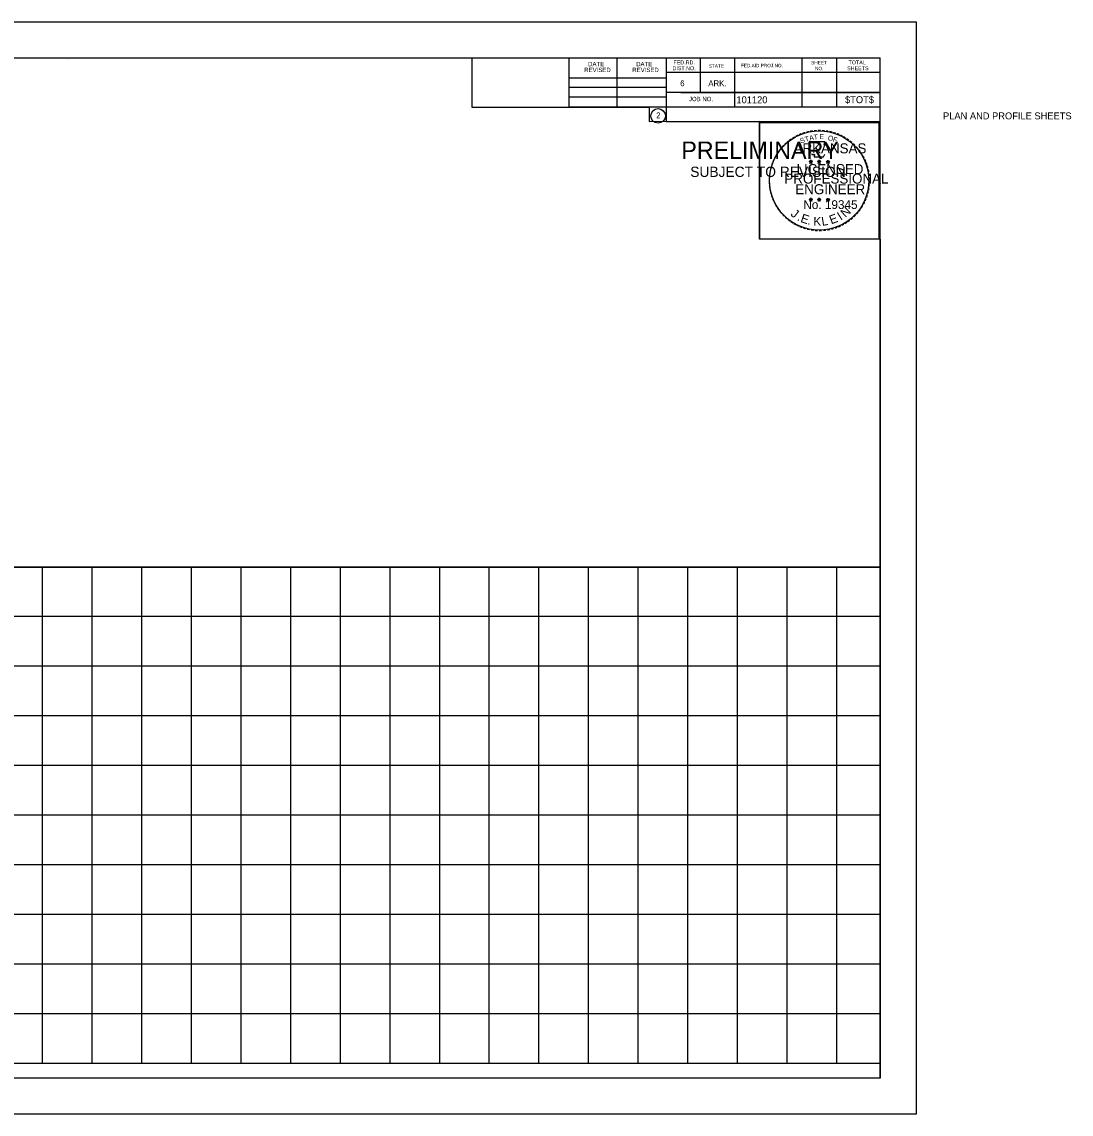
# Model space of a CAD drawing. Extents: x 1369502 to 1371590, y 379102 to 380202.
# Drawn here: x 1370533 to 1371590, y 379102 to 380202 of the extents above; entities that cross this region are included whole.
import ezdxf

# ---------------------------------------------------------------- set-up
doc = ezdxf.new("R2010")
doc.units = 0
for name, color, linetype in [('Level 63', 7, 'Continuous'), ('R_Border', 7, 'Continuous'), ('R_Border Notes', 7, 'Continuous'), ('R_Border PE', 7, 'Continuous'), ('R_Border Prem', 7, 'Continuous'), ('R_Grid', 7, 'Continuous'), ('R_No Plot', 7, 'Continuous')]:
    doc.layers.add(name, color=color, linetype=linetype)

msp = doc.modelspace()

# ---------------------------------------------------------------- linework, layer by layer
at = {"layer": 'Level 63'}
msp.add_lwpolyline([(1369733.7, 380202.4), (1371433.7, 380202.4), (1371433.7, 379102.4), (1369733.7, 379102.4)], close=True, dxfattribs=at)
at = {"layer": 'R_Border'}
for p, q in [((1369816.4, 380166), (1371397.3, 380166)), ((1370579, 380164.7), (1370579, 380164.7)), ((1370579, 380164.7), (1370579, 380164.7)), ((1371084.1, 380116.6), (1371084.1, 380166)), ((1371132.5, 380116.6), (1371132.5, 380166)), ((1371181.8, 380166), (1371181.8, 380102)), ((1371216, 380166), (1371216, 380131.3)), ((1371250.7, 380166), (1371250.7, 380116.6)), ((1371318.6, 380166), (1371318.6, 380116.6)), ((1371353.3, 380166), (1371353.3, 380116.6)), ((1371397.3, 379138.7), (1371397.3, 380166)), ((1371397.3, 380151.3), (1371181.8, 380151.3)), ((1371397.3, 380151.4), (1371397.3, 380151.4)), ((1371084.1, 380145.9), (1371181.8, 380145.9)), ((1371084.1, 380136.6), (1371181.8, 380136.6)), ((1371397.3, 380131.3), (1371181.8, 380131.3)), ((1371196.6, 380131.3), (1371397.3, 380131.3)), ((1371084.1, 380126.9), (1371181.8, 380126.9)), ((1371397.3, 380116.6), (1371084.1, 380116.6)), ((1371181.8, 380102), (1371397.3, 380102)), ((1371397.3, 379138.7), (1369816.4, 379138.7))]:
    msp.add_line(p, q, dxfattribs=at)
msp.add_circle((1371173.7, 380107.7), 7.33, dxfattribs=at)
at = {"layer": 'R_Border Notes'}
msp.add_line((1371397.3, 379653.4), (1369816.4, 379653.4), dxfattribs=at)
at = {"layer": 'R_Border PE'}
for p, q in [((1371325.8, 380062), (1371327.5, 380061.4)), ((1371325.8, 380062), (1371327.1, 380061.8)), ((1371325.8, 380062), (1371327, 380061.4)), ((1371326.4, 380059.9), (1371327.5, 380061.4)), ((1371326.4, 380059.9), (1371327.1, 380061.2)), ((1371326.4, 380059.9), (1371327.5, 380061)), ((1371327.5, 380063.3), (1371327.3, 380062)), ((1371327.5, 380061.4), (1371327.5, 380063.3)), ((1371327.5, 380063.3), (1371327.8, 380062.1)), ((1371329.2, 380062), (1371327.5, 380061.4)), ((1371328.6, 380059.9), (1371327.5, 380061.4)), ((1371328.6, 380059.9), (1371327.5, 380061)), ((1371329.2, 380062), (1371327.8, 380061.7)), ((1371328.6, 380059.9), (1371327.9, 380061.4)), ((1371329.2, 380062), (1371328.3, 380061.5)), ((1371334.2, 380062), (1371336, 380061.4)), ((1371334.2, 380062), (1371335.5, 380061.8)), ((1371334.2, 380062), (1371335.4, 380061.4)), ((1371334.8, 380059.9), (1371336, 380061.4)), ((1371334.8, 380059.9), (1371335.5, 380061.2)), ((1371334.8, 380059.9), (1371335.9, 380061)), ((1371336, 380063.3), (1371335.8, 380062)), ((1371337, 380059.9), (1371335.9, 380061)), ((1371336, 380061.4), (1371336, 380063.3)), ((1371336, 380063.3), (1371336.2, 380062.1)), ((1371337.7, 380062), (1371336, 380061.4)), ((1371337, 380059.9), (1371336, 380061.4)), ((1371337.7, 380062), (1371336.2, 380061.7)), ((1371337, 380059.9), (1371336.3, 380061.4)), ((1371337.7, 380062), (1371336.7, 380061.5)), ((1371343.1, 380061.9), (1371344.8, 380061.4)), ((1371343.1, 380061.9), (1371344.3, 380061.7)), ((1371343.1, 380061.9), (1371344.3, 380061.3)), ((1371343.7, 380059.9), (1371344.8, 380061.4)), ((1371343.7, 380059.9), (1371344.4, 380061.1)), ((1371344.8, 380063.2), (1371344.6, 380061.9)), ((1371344.8, 380061.4), (1371344.8, 380063.2)), ((1371344.8, 380063.2), (1371345.1, 380061.9)), ((1371346.6, 380061.9), (1371344.8, 380061.4)), ((1371345.9, 380059.9), (1371344.8, 380061.4)), ((1371346.6, 380061.9), (1371345.1, 380061.7)), ((1371345.9, 380059.9), (1371345.2, 380061.3)), ((1371346.6, 380061.9), (1371345.5, 380061.4)), ((1371343.7, 380059.9), (1371344.8, 380061)), ((1371345.9, 380059.9), (1371344.8, 380061)), ((1371325.7, 380023.8), (1371327.5, 380023.3)), ((1371325.7, 380023.8), (1371327.1, 380023.6)), ((1371325.7, 380023.8), (1371327, 380023.2)), ((1371326.4, 380021.8), (1371327.5, 380023.3)), ((1371326.4, 380021.8), (1371327.1, 380023)), ((1371326.4, 380021.8), (1371327.5, 380022.9)), ((1371327.5, 380025.1), (1371327.3, 380023.8)), ((1371327.5, 380023.3), (1371327.5, 380025.1)), ((1371327.5, 380025.1), (1371327.7, 380023.8)), ((1371329.2, 380023.8), (1371327.5, 380023.3)), ((1371328.6, 380021.8), (1371327.5, 380023.3)), ((1371328.6, 380021.8), (1371327.5, 380022.9)), ((1371329.2, 380023.8), (1371327.8, 380023.6)), ((1371328.6, 380021.8), (1371327.9, 380023.2)), ((1371329.2, 380023.8), (1371328.3, 380023.3)), ((1371334.2, 380023.8), (1371335.9, 380023.3)), ((1371334.2, 380023.8), (1371335.5, 380023.6)), ((1371334.2, 380023.8), (1371335.4, 380023.2)), ((1371334.8, 380021.8), (1371335.9, 380023.3)), ((1371334.8, 380021.8), (1371335.5, 380023)), ((1371334.8, 380021.8), (1371335.9, 380022.9)), ((1371335.9, 380025.1), (1371335.7, 380023.8)), ((1371335.9, 380023.3), (1371335.9, 380025.1)), ((1371335.9, 380025.1), (1371336.1, 380023.8)), ((1371337.7, 380023.8), (1371335.9, 380023.3)), ((1371337, 380021.8), (1371335.9, 380023.3)), ((1371337, 380021.8), (1371335.9, 380022.9)), ((1371337.7, 380023.8), (1371336.2, 380023.6)), ((1371337, 380021.8), (1371336.3, 380023.2)), ((1371337.7, 380023.8), (1371336.6, 380023.3)), ((1371343.1, 380023.8), (1371344.8, 380023.2)), ((1371343.1, 380023.8), (1371344.3, 380023.5)), ((1371343.1, 380023.8), (1371344.3, 380023.2)), ((1371343.7, 380021.7), (1371344.8, 380023.2)), ((1371343.7, 380021.7), (1371344.4, 380023)), ((1371343.7, 380021.7), (1371344.8, 380022.9)), ((1371344.8, 380025), (1371344.6, 380023.8)), ((1371344.8, 380023.2), (1371344.8, 380025)), ((1371344.8, 380025), (1371345.1, 380023.8)), ((1371346.6, 380023.8), (1371344.8, 380023.2)), ((1371345.9, 380021.7), (1371344.8, 380023.2)), ((1371345.9, 380021.7), (1371344.8, 380022.8)), ((1371346.6, 380023.8), (1371345.1, 380023.5)), ((1371345.9, 380021.7), (1371345.2, 380023.2)), ((1371346.6, 380023.8), (1371345.5, 380023.3))]:
    msp.add_line(p, q, dxfattribs=at)
for points in [[(1371326, 380081.5), (1371327.3, 380077.3)], [(1371343.7, 380076.9), (1371344.4, 380078.3), (1371341, 380078.2), (1371341.6, 380081.5), (1371326, 380081.5)], [(1371327.5, 380063.3), (1371328.6, 380059.9), (1371325.8, 380062), (1371329.2, 380062), (1371326.4, 380059.9), (1371327.5, 380063.3)], [(1371328.5, 380069.4), (1371328.5, 380068.9), (1371331.3, 380068.8), (1371331, 380066.4), (1371340.4, 380066.4), (1371341.5, 380069.1)], [(1371336, 380063.3), (1371337, 380059.9), (1371334.2, 380062), (1371337.7, 380062), (1371334.8, 380059.9), (1371336, 380063.3)], [(1371344.8, 380063.2), (1371345.9, 380059.9), (1371343.1, 380061.9), (1371346.6, 380061.9), (1371343.7, 380059.9), (1371344.8, 380063.2)], [(1371327.5, 380025.1), (1371328.6, 380021.8), (1371325.7, 380023.8), (1371329.2, 380023.8), (1371326.4, 380021.8), (1371327.5, 380025.1)], [(1371335.9, 380025.1), (1371337, 380021.8), (1371334.2, 380023.8), (1371337.7, 380023.8), (1371334.8, 380021.8), (1371335.9, 380025.1)], [(1371344.8, 380025), (1371345.9, 380021.7), (1371343.1, 380023.8), (1371346.6, 380023.8), (1371343.7, 380021.7), (1371344.8, 380025)]]:
    msp.add_lwpolyline(points, dxfattribs=at)
for centre, radius in [((1371336, 380042.6), 50), ((1371327.5, 380061.4), 0.868), ((1371327.5, 380061.4), 0.728), ((1371327.5, 380061.4), 0.583), ((1371327.5, 380061.4), 0.499), ((1371327.5, 380061.4), 0.377), ((1371327.5, 380061.4), 0.25), ((1371327.5, 380061.4), 0.149), ((1371335.9, 380061.4), 0.868), ((1371335.9, 380061.4), 0.728), ((1371335.9, 380061.4), 0.583), ((1371335.9, 380061.4), 0.499), ((1371335.9, 380061.4), 0.377), ((1371335.9, 380061.4), 0.25), ((1371335.9, 380061.4), 0.149), ((1371344.8, 380061.4), 0.868), ((1371344.8, 380061.4), 0.728), ((1371344.8, 380061.4), 0.583), ((1371344.8, 380061.4), 0.499), ((1371344.8, 380061.4), 0.377), ((1371344.8, 380061.4), 0.25), ((1371344.8, 380061.4), 0.149), ((1371327.5, 380023.3), 0.868), ((1371327.5, 380023.3), 0.728), ((1371327.5, 380023.3), 0.583), ((1371327.5, 380023.3), 0.499), ((1371327.5, 380023.3), 0.377), ((1371327.5, 380023.3), 0.25), ((1371327.5, 380023.3), 0.149), ((1371335.9, 380023.3), 0.868), ((1371335.9, 380023.3), 0.728), ((1371335.9, 380023.3), 0.583), ((1371335.9, 380023.3), 0.499), ((1371335.9, 380023.3), 0.377), ((1371335.9, 380023.3), 0.25), ((1371335.9, 380023.3), 0.149), ((1371344.8, 380023.2), 0.868), ((1371344.8, 380023.2), 0.728), ((1371344.8, 380023.2), 0.583), ((1371344.8, 380023.2), 0.499), ((1371344.8, 380023.2), 0.377), ((1371344.8, 380023.2), 0.25), ((1371344.8, 380023.2), 0.149)]:
    msp.add_circle(centre, radius, dxfattribs=at)
at = {"layer": 'R_Grid'}
for p, q in [((1370553.7, 379153.4), (1370553.7, 379653.4)), ((1370603.7, 379153.4), (1370603.7, 379653.4)), ((1370653.7, 379153.4), (1370653.7, 379653.4)), ((1370703.7, 379153.4), (1370703.7, 379653.4)), ((1370753.7, 379153.4), (1370753.7, 379653.4)), ((1370803.7, 379153.4), (1370803.7, 379653.4)), ((1370853.7, 379153.4), (1370853.7, 379653.4)), ((1370903.7, 379153.4), (1370903.7, 379653.4)), ((1370953.7, 379153.4), (1370953.7, 379653.4)), ((1371003.7, 379153.4), (1371003.7, 379653.4)), ((1371053.7, 379153.4), (1371053.7, 379653.4)), ((1371103.7, 379153.4), (1371103.7, 379653.4)), ((1371153.7, 379153.4), (1371153.7, 379653.4)), ((1371203.7, 379153.4), (1371203.7, 379653.4)), ((1371253.7, 379153.4), (1371253.7, 379653.4)), ((1371303.7, 379153.4), (1371303.7, 379653.4)), ((1371353.7, 379153.4), (1371353.7, 379653.4)), ((1371397.3, 379603.4), (1369816.4, 379603.4)), ((1371397.3, 379553.4), (1369816.4, 379553.4)), ((1371397.3, 379503.4), (1369816.4, 379503.4)), ((1371397.3, 379453.4), (1369816.4, 379453.4)), ((1371397.3, 379403.4), (1369816.4, 379403.4)), ((1371397.3, 379353.4), (1369816.4, 379353.4)), ((1371397.3, 379303.4), (1369816.4, 379303.4)), ((1371397.3, 379253.4), (1369816.4, 379253.4)), ((1371397.3, 379203.4), (1369816.4, 379203.4)), ((1371397.3, 379153.4), (1369816.4, 379153.4))]:
    msp.add_line(p, q, dxfattribs=at)
at = {"layer": 'R_No Plot'}
for points in [[(1370986, 380166), (1370986, 380116.6), (1371164.7, 380116.6), (1371164.7, 380102), (1371275.9, 380102.4), (1371275.9, 379984), (1371397.3, 379983.7), (1371397.3, 379653.4), (1369816.4, 379653.4), (1369816.4, 380166)], [(1371275.9, 380101.1), (1371396.2, 380101.1), (1371396.2, 379983.7), (1371275.9, 379983.7)], [(1371397.3, 379653.4), (1371397.3, 379138.7), (1369816.4, 379138.7), (1369816.4, 379653.4)]]:
    msp.add_lwpolyline(points, close=True, dxfattribs=at)

# ---------------------------------------------------------------- texts
at = {"layer": 'R_Border'}
for s, height, p in [('DATE', 4.4, (1371103.2, 380157.7)), ('DATE', 4.4, (1371151.6, 380157.7)), ('FED.RD.', 3.91, (1371189.2, 380159.6)), ('FED.AID PROJ.NO.', 3.42, (1371257.1, 380156.7)), ('SHEET', 3.42, (1371327.9, 380159.6)), ('TOTAL', 3.91, (1371365.5, 380159.6)), ('REVISED', 4.4, (1371099.3, 380151.8)), ('REVISED', 4.4, (1371147.7, 380151.8)), ('DIST.NO.', 3.91, (1371188.2, 380153.7)), ('STATE', 3.42, (1371224.8, 380156.2)), ('NO.', 3.42, (1371331.8, 380153.7)), ('SHEETS', 3.91, (1371364.1, 380153.7)), ('6', 5.86, (1371196, 380137.6)), ('ARK.', 5.86, (1371224.3, 380137.6)), ('JOB NO.', 4.4, (1371204.8, 380122.5)), ('101120', 7, (1371252.6, 380120.4)), ('$TOT$', 7, (1371362, 380120.5)), ('2', 5.86, (1371171.8, 380105.3)), ('PLAN AND PROFILE SHEETS', 7, (1371460.7, 380104.2))]:
    msp.add_text(s, height=height, rotation=360, dxfattribs=at).set_placement(p)
at = {"layer": 'R_Border PE'}
for s, height, rotation, p in [('-', 8.06, 38.9507, (1371305, 380078.5)), ('-', 8.06, 36.2317, (1371307.3, 380080.5)), ('-', 8.06, 34.0636, (1371310.3, 380082.4)), ('-', 8.06, 28.7918, (1371313.3, 380084.3)), ('-', 8.06, 24.3072, (1371316.4, 380085.9)), ('S', 5.04, 21.594, (1371317.7, 380079.9)), ('-', 8.06, 19.1761, (1371319.7, 380087.2)), ('T', 5.04, 16.4036, (1371322.3, 380081.6)), ('-', 8.06, 13.6301, (1371323.5, 380088.4)), ('A', 5.04, 11.2132, (1371326.4, 380082.8)), ('-', 8.06, 10.2193, (1371326.9, 380089.3)), ('T', 5.04, 6.0228, (1371330.7, 380083.7)), ('-', 8.06, 5.8968, (1371330.5, 380089.8)), ('-', 8.06, 0.1862, (1371334.4, 380090.1)), ('E', 5.04, 0.8323, (1371336.3, 380084.3)), ('-', 8.06, 357.743, (1371338.1, 380090.1)), ('-', 8.06, 352.1617, (1371341.8, 380089.8)), ('O', 5.04, 350.4515, (1371344.4, 380083.2)), ('-', 8.06, 347.2049, (1371345.4, 380089.3)), ('F', 5.04, 340.0707, (1371349.2, 380082.1)), ('-', 8.06, 342.3362, (1371348.7, 380088.4)), ('-', 8.06, 337.8551, (1371352.3, 380087.4)), ('-', 8.06, 334.1211, (1371355.5, 380086)), ('-', 8.06, 329.6409, (1371358.4, 380084.6)), ('-', 8.06, 325.8627, (1371361.6, 380082.7)), ('-', 8.06, 320.5297, (1371364.8, 380080.6)), ('-', 8.06, 54.2325, (1371296.4, 380068.7)), ('-', 8.06, 50.6142, (1371298.4, 380071.6)), ('-', 8.06, 48.4231, (1371300.5, 380074)), ('-', 8.06, 42.9622, (1371302.8, 380076.4)), ('-', 8.06, 315.5786, (1371367.8, 380078.1)), ('-', 8.06, 309.8797, (1371370.6, 380075.3)), ('-', 8.06, 306.6522, (1371373.3, 380072.3)), ('-', 8.06, 67.7743, (1371291.9, 380059.9)), ('-', 8.06, 62.8713, (1371293.2, 380062.9)), ('-', 8.06, 58.0706, (1371294.8, 380066)), ('-', 7.05, 303.6753, (1371375.7, 380069.5)), ('-', 8.06, 299.6684, (1371377.3, 380066.4)), ('-', 8.06, 294.6628, (1371379, 380063.3)), ('-', 8.06, 290.5728, (1371380.3, 380060.4)), ('-', 8.06, 81.2013, (1371289.2, 380049.5)), ('-', 8.06, 75.461, (1371289.8, 380053.1)), ('-', 8.06, 72.3945, (1371290.8, 380056.7)), ('-', 8.06, 285.1233, (1371381.4, 380057.5)), ('-', 8.06, 280.5493, (1371382.5, 380053.7)), ('-', 8.06, 94.1959, (1371288.8, 380038.8)), ('-', 8.06, 89.0622, (1371288.6, 380042.5)), ('-', 8.06, 85.1863, (1371288.8, 380046)), ('-', 8.06, 276.5962, (1371383.3, 380049.9)), ('-', 8.06, 274.3301, (1371383.6, 380046.2)), ('-', 8.06, 269.9407, (1371383.7, 380043)), ('-', 8.06, 98.9479, (1371289.2, 380035.5)), ('-', 8.06, 101.7149, (1371289.8, 380031.8)), ('-', 8.06, 105.4578, (1371290.7, 380028.8)), ('-', 8.06, 252.8681, (1371381.8, 380029.3)), ('-', 8.06, 255.7626, (1371382.7, 380033)), ('-', 8.06, 260.9953, (1371383.3, 380036.4)), ('-', 8.06, 263.5172, (1371383.6, 380039.7)), ('-', 8.06, 109.0874, (1371291.7, 380025.6)), ('-', 8.06, 114.0643, (1371293, 380022.6)), ('-', 8.06, 115.7289, (1371294.6, 380019.5)), ('-', 8.06, 120.4471, (1371296.4, 380016.5)), ('-', 8.06, 239.0712, (1371377.4, 380019)), ('-', 8.06, 244.6197, (1371379.4, 380022.8)), ('-', 8.06, 247.8887, (1371380.7, 380026)), ('-', 8.06, 125.8934, (1371298.3, 380013.7)), ('-', 8.06, 130.7181, (1371300.7, 380010.9)), ('-', 8.06, 134.2238, (1371303.3, 380008.2)), ('J', 8.85, 323.9056, (1371306.6, 380007.6)), ('E', 8.85, 340.8881, (1371316.5, 380001.1)), ('E', 8.85, 20.5042, (1371348.1, 379998.4)), ('I', 8.85, 32.2382, (1371357.5, 380002.2)), ('N', 8.85, 42.9205, (1371362.4, 380004.8)), ('-', 8.06, 225.7653, (1371370.8, 380010.1)), ('-', 8.06, 231.2538, (1371373.2, 380012.9)), ('-', 8.06, 233.8452, (1371375.4, 380015.8)), ('-', 8.06, 138.9338, (1371306, 380005.9)), ('-', 8.06, 144.6463, (1371308.8, 380003.8)), ('-', 8.06, 148.0898, (1371311.6, 380001.9)), ('-', 8.06, 151.5704, (1371314.5, 380000.3)), ('-', 8.06, 154.6002, (1371317.2, 379999.1)), ('.', 8.85, 336.3407, (1371313.2, 380002.8)), ('-', 8.06, 158.5612, (1371320.3, 379997.8)), ('-', 8.06, 162.7983, (1371323.7, 379996.7)), ('.', 8.85, 350.694, (1371323.8, 379998.4)), ('K', 8.85, 359.3149, (1371330.1, 379997.1)), ('L', 8.85, 8.7702, (1371338.9, 379996.9)), ('-', 8.06, 200.7184, (1371353.7, 379998.4)), ('-', 8.06, 204.2516, (1371356.8, 379999.7)), ('-', 8.06, 207.3568, (1371359.9, 380001.4)), ('-', 8.06, 212.2491, (1371362.7, 380003.2)), ('-', 8.06, 215.7363, (1371365.4, 380005.1)), ('-', 8.06, 221.0851, (1371368.2, 380007.5)), ('-', 8.06, 167.5555, (1371327.3, 379995.9)), ('-', 8.06, 173.1155, (1371331.2, 379995.3)), ('-', 8.06, 176.5183, (1371335, 379995)), ('-', 8.06, 181.5918, (1371338.8, 379995.1)), ('-', 8.06, 185.8167, (1371342.8, 379995.5)), ('-', 8.06, 191.2858, (1371346.6, 379996.2)), ('-', 8.06, 195.4743, (1371350.2, 379997.2))]:
    msp.add_text(s, height=height, rotation=rotation, dxfattribs=at).set_placement(p)
for s, height, p in [('ARKANSAS', 10.08, (1371310.1, 380070)), ('LICENSED', 10.08, (1371313.1, 380049.1)), ('PROFESSIONAL', 10.078, (1371300.9, 380039.5)), ('ENGINEER', 10.08, (1371311.9, 380028.8)), ('No. 19345', 8.85, (1371320, 380013.9))]:
    msp.add_text(s, height=height, dxfattribs=at).set_placement(p)
at = {"layer": 'R_Border Prem'}
for s, height, p in [('PRELIMINARY', 17.5, (1371197.1, 380064.4)), ('DWB', 0.1, (1371200.8, 380073.6)), ('SUBJECT TO REVISION', 10.376, (1371206.1, 380046.2))]:
    msp.add_text(s, height=height, rotation=360, dxfattribs=at).set_placement(p)

doc.saveas('drawing.dxf')
